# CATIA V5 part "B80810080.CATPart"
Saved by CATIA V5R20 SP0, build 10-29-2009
Part number: B80810080
Revision: 2
Definition: design
Nomenclature: B80810080
Source: made
Description: NOT SPECIFIED
Bounding box of the stored display mesh (mm): x -6.824 to 6.824, y -7 to 7, z 0 to 80
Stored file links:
  C:\Users\Raffaele\Desktop\3D X SITO CF\BOLEX\4-PILLAR REF 808\B80810080.CATPart
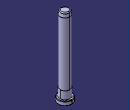
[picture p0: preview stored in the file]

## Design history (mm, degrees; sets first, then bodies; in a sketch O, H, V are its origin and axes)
Body1 "MANIFOLD_SOLID_BREP #450" (main body)
  Solid1: solid without history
